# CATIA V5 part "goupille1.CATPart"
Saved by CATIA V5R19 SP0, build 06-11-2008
Part number: goupille.1
Bounding box of the stored display mesh (mm): x 0 to 20, y -2.5 to 2.5, z -2.5 to 2.5
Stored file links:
  C:\Documents and Settings\alenoir\Bureau\mécanisme\goupille1.CATPart
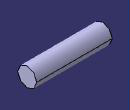
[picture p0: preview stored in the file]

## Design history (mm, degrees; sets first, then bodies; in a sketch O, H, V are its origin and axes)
Body1 (main body)
  Sketch1 on yz-plane, origin (0, 0, 0), H (0, 1, 0), V (0, 0, 1)
    circle A1 centre (0, 0) radius 2.5
    radius A1 = 2.5
  Pad1: profile Sketch1, direction (1, 0, 0), length 20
